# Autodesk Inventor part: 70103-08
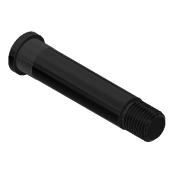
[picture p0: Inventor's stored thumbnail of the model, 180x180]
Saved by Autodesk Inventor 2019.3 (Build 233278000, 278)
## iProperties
Created: 2012-10
Part Number: 70103-08
Material: Ogólny
Document SubType Name: Modeling
Designer: CADENGINEERING4
Density: 1 g/cm^3
Appearance: Gładki — czarny
Author: CADENGINEERING4
Revision Number: ÈÎºÎ
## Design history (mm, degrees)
feature "ÕóÁÐ(Ô²ÖÜ)1"
node "Bryła1"
